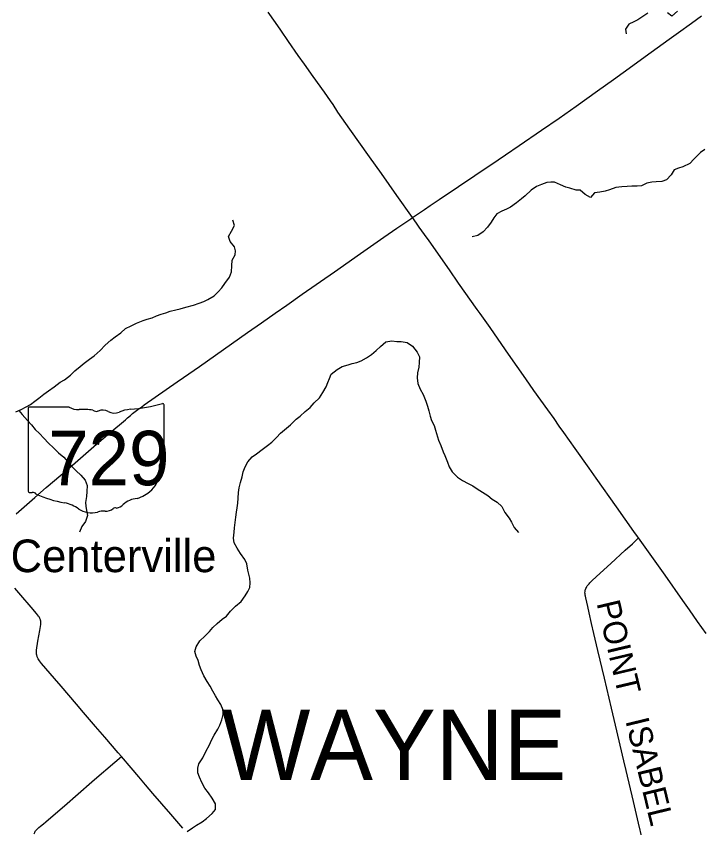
# Model space of a CAD drawing. Extents: x 0 to 34, y 0 to 22.
# Drawn here: x 3.432 to 5.101, y 18.098 to 20.064 of the extents above; entities that cross this region are included whole.
import ezdxf

# ---------------------------------------------------------------- set-up
doc = ezdxf.new("R2010")
doc.units = 0
for name, color, linetype in [('GM_X_County_Road', 7, 'Continuous'), ('GM_X_Minor_River', 7, 'Continuous'), ('GM_X_State_Location', 7, 'Continuous'), ('GM_X_State_Route', 7, 'Continuous'), ('GM_X_State_Shield', 7, 'Continuous'), ('GM_X_Township_Road', 7, 'Continuous'), ('GM_X_Township_Road_Text', 7, 'Continuous'), ('GM_X_Township_Text', 7, 'Continuous'), ('GM_X_Unincorporated_Text', 7, 'Continuous')]:
    doc.layers.add(name, color=color, linetype=linetype)

msp = doc.modelspace()

# ---------------------------------------------------------------- linework, layer by layer
at = {"layer": 'GM_X_County_Road'}
for points in [[(3.6866, 18.27), (3.6787, 18.2792), (3.6462, 18.3169), (3.6242, 18.3429), (3.595, 18.3769), (3.5777, 18.3972), (3.5405, 18.4406), (3.5248, 18.4591), (3.4932, 18.4958), (3.4883, 18.5021), (3.4852, 18.5067), (3.4843, 18.5083), (3.4835, 18.5099), (3.4826, 18.5117), (3.4821, 18.5132), (3.4817, 18.5146), (3.4813, 18.5161), (3.4811, 18.5179), (3.4808, 18.5197), (3.4808, 18.5217), (3.4807, 18.5239), (3.481, 18.5282), (3.4843, 18.5496), (3.4892, 18.5759), (3.4915, 18.59), (3.4916, 18.5918), (3.4917, 18.5938), (3.4917, 18.5952), (3.4915, 18.5971), (3.4912, 18.5985), (3.4908, 18.6002), (3.4903, 18.6017), (3.4898, 18.6033), (3.4889, 18.605), (3.4881, 18.6067), (3.4869, 18.6085), (3.4856, 18.6104), (3.4806, 18.6168), (3.4678, 18.6321), (3.4432, 18.6609), (3.4283, 18.6784)], [(3.4749, 18.0827), (3.4756, 18.0847), (3.4764, 18.0862), (3.4771, 18.0877), (3.4779, 18.0888), (3.4786, 18.0899), (3.4795, 18.091), (3.4808, 18.0924), (3.4827, 18.0944), (3.4864, 18.0979), (3.4902, 18.1011), (3.4974, 18.1071), (3.5031, 18.1119), (3.5555, 18.1568), (3.5751, 18.174), (3.6216, 18.2143), (3.6711, 18.2567), (3.6866, 18.27)], [(3.8358, 18.0965), (3.8061, 18.1308), (3.7632, 18.1807), (3.7454, 18.2014), (3.7288, 18.2207), (3.7103, 18.2425), (3.6866, 18.27)]]:
    msp.add_lwpolyline(points, dxfattribs=at)
at = {"layer": 'GM_X_Minor_River'}
for points in [[(5.0344, 20.0759), (5.021, 20.0635), (5.0105, 20.0723)], [(4.963, 20.0715), (4.9508, 20.0633), (4.9386, 20.0554), (4.929, 20.0505), (4.9165, 20.0445), (4.9088, 20.0324), (4.9102, 20.021)], [(5.1009, 19.7409), (5.0902, 19.7334), (5.0741, 19.7172), (5.0642, 19.707), (5.0474, 19.6992), (5.0375, 19.6958), (5.0269, 19.6913), (5.0195, 19.6792), (5.0084, 19.6676), (4.997, 19.6631), (4.9833, 19.6624), (4.9727, 19.6621), (4.9605, 19.6592), (4.9472, 19.6532), (4.9369, 19.6521), (4.9236, 19.6519), (4.9126, 19.6512), (4.8997, 19.6505), (4.8856, 19.6487), (4.8696, 19.6428), (4.8594, 19.6398), (4.8468, 19.6372), (4.8335, 19.6362), (4.8239, 19.6245), (4.8107, 19.6322), (4.7986, 19.6422), (4.7891, 19.6426), (4.774, 19.6469), (4.7641, 19.65), (4.7513, 19.655), (4.7369, 19.6616), (4.7274, 19.6621), (4.7179, 19.6606), (4.7053, 19.6561), (4.6927, 19.6513), (4.6801, 19.6423), (4.6653, 19.6289)], [(4.6653, 19.6289), (4.6567, 19.6214), (4.6444, 19.612), (4.6298, 19.6008), (4.6203, 19.5963), (4.6092, 19.5915), (4.5969, 19.5852), (4.5896, 19.5754), (4.5826, 19.5648), (4.5741, 19.5524), (4.5637, 19.5411), (4.5506, 19.5329), (4.5373, 19.5289)], [(3.4311, 19.1055), (3.4434, 19.1111), (3.4556, 19.1178), (3.466, 19.1234), (3.4767, 19.1308), (3.4863, 19.1383), (3.499, 19.1481), (3.5097, 19.1559), (3.5236, 19.1657), (3.5382, 19.1769), (3.5489, 19.1825), (3.5635, 19.1941), (3.5735, 19.2046), (3.5866, 19.2155), (3.5962, 19.223), (3.6096, 19.2327), (3.6207, 19.2413), (3.635, 19.2541), (3.6469, 19.2665), (3.6607, 19.2789), (3.6719, 19.2871), (3.6849, 19.2964), (3.6968, 19.3073), (3.7102, 19.314), (3.7233, 19.3199), (3.7397, 19.3266), (3.7492, 19.3295), (3.7611, 19.3332), (3.7714, 19.3376), (3.7833, 19.3421), (3.7943, 19.3454), (3.805, 19.349), (3.8184, 19.3527), (3.8294, 19.3548), (3.8428, 19.3585), (3.8611, 19.3636), (3.8753, 19.3684), (3.8863, 19.3724), (3.8959, 19.3776), (3.9116, 19.3866), (3.9216, 19.396), (3.9301, 19.4058), (3.9375, 19.4163), (3.9487, 19.4318), (3.9534, 19.4446), (3.954, 19.4594), (3.9553, 19.4724), (3.9623, 19.4856), (3.9631, 19.4951), (3.9606, 19.505), (3.9501, 19.518), (3.9464, 19.5302), (3.9534, 19.543), (3.9608, 19.5566), (3.9568, 19.57)], [(4.0039, 18.9961), (4.0139, 19.0032), (4.0278, 19.0144), (4.0404, 19.0234), (4.0516, 19.032), (4.0623, 19.0429), (4.0724, 19.0535), (4.0866, 19.0655), (4.0962, 19.0741), (4.11, 19.0872), (4.1197, 19.0951), (4.132, 19.1064), (4.1443, 19.1161), (4.1543, 19.127), (4.167, 19.139), (4.1747, 19.1522), (4.1829, 19.1662), (4.1872, 19.1764), (4.1908, 19.1862), (4.1954, 19.1965), (4.2093, 19.2081), (4.2219, 19.2148), (4.236, 19.2192), (4.246, 19.2225), (4.2574, 19.225), (4.2677, 19.2291), (4.2804, 19.2365), (4.2926, 19.244), (4.3046, 19.2537), (4.315, 19.2639), (4.3276, 19.2748), (4.3418, 19.2776), (4.3543, 19.2756), (4.3649, 19.2755), (4.379, 19.273), (4.3922, 19.2645), (4.4034, 19.2496), (4.4094, 19.2389), (4.4088, 19.2252), (4.4076, 19.2138), (4.4047, 19.2002), (4.4035, 19.188), (4.4056, 19.1736), (4.4107, 19.1606), (4.4178, 19.1472), (4.4248, 19.1312), (4.4285, 19.1194), (4.4318, 19.1075), (4.4354, 19.095), (4.4387, 19.0847), (4.4447, 19.0724), (4.448, 19.061), (4.4557, 19.037), (4.4612, 19.024), (4.4667, 19.0087), (4.4704, 18.9992), (4.4771, 18.9832), (4.4808, 18.9721), (4.4882, 18.9599), (4.5014, 18.9468), (4.5134, 18.9387), (4.5274, 18.9313), (4.5384, 18.9262), (4.5494, 18.9189), (4.5622, 18.9108), (4.575, 18.903), (4.5852, 18.8938), (4.5973, 18.8864), (4.6089, 18.8757), (4.6164, 18.8612), (4.6269, 18.8477), (4.6325, 18.8378), (4.6388, 18.8248), (4.6489, 18.8129)], [(3.4383, 19.1088), (3.4459, 19.0985), (3.4587, 19.0847), (3.4684, 19.0736), (3.4774, 19.0624), (3.488, 19.0525), (3.4985, 19.0417), (3.5101, 19.0294), (3.5218, 19.0183), (3.5342, 19.0063), (3.5474, 18.9952), (3.5575, 18.9833), (3.5654, 18.9733), (3.5767, 18.9622), (3.5883, 18.9522), (3.5992, 18.9399), (3.6036, 18.9269), (3.6031, 18.9125), (3.6018, 18.9003), (3.5997, 18.8859), (3.6007, 18.8764), (3.6021, 18.8665), (3.6043, 18.854), (3.5999, 18.8399), (3.591, 18.8275), (3.5851, 18.8135)], [(3.8461, 18.0884), (3.8588, 18.0977), (3.8688, 18.1037), (3.8822, 18.1119), (3.8933, 18.1197), (3.9068, 18.1321), (3.9149, 18.1419), (3.9147, 18.1556), (3.9065, 18.169), (3.8975, 18.182), (3.8889, 18.1935), (3.8814, 18.2073), (3.8763, 18.2206), (3.8718, 18.2305), (3.8716, 18.2423), (3.8744, 18.2525), (3.8841, 18.2672), (3.8915, 18.2827), (3.9, 18.2982), (3.9047, 18.3096), (3.9113, 18.322), (3.9203, 18.3364), (3.925, 18.3462), (3.9304, 18.3594), (3.9333, 18.3719), (3.9334, 18.3829), (3.9275, 18.3963), (3.9204, 18.4074), (3.9144, 18.417), (3.9085, 18.4288), (3.9017, 18.4407), (3.8943, 18.4521), (3.8868, 18.4655), (3.8798, 18.48), (3.8761, 18.4907), (3.8728, 18.5029), (3.868, 18.5132), (3.8647, 18.5247), (3.8679, 18.536), (3.8764, 18.5504), (3.8891, 18.562), (3.9003, 18.5733), (3.908, 18.5831), (3.9184, 18.5921), (3.9311, 18.6026), (3.9418, 18.61), (3.9515, 18.6221), (3.9631, 18.6349), (3.9773, 18.6457), (3.9866, 18.6597), (3.9932, 18.6699), (3.9979, 18.6801), (3.9991, 18.6907), (3.9977, 18.7021), (3.9952, 18.712), (3.993, 18.7219), (3.9909, 18.7368), (3.9861, 18.7474), (3.9753, 18.762), (3.967, 18.7754), (3.9603, 18.7876), (3.9582, 18.7994), (3.9599, 18.8138), (3.9612, 18.8245), (3.9625, 18.8374), (3.9641, 18.8503), (3.9654, 18.8624), (3.9671, 18.8727), (3.9691, 18.8844), (3.97, 18.8958), (3.9706, 18.9099), (3.9718, 18.9209), (3.975, 18.9341), (3.979, 18.9477), (3.9822, 18.9599), (3.9869, 18.9724), (3.9931, 18.9841), (4.0039, 18.9961)]]:
    msp.add_lwpolyline(points, dxfattribs=at)
at = {"layer": 'GM_X_State_Route'}
for points in [[(4.4087, 19.5527), (4.4016, 19.5626), (4.3921, 19.5761), (4.3545, 19.6298), (4.3169, 19.6831), (4.288, 19.7235), (4.2406, 19.7905), (4.2117, 19.8317), (4.1996, 19.8497), (4.1935, 19.8584), (4.1786, 19.8798), (4.1517, 19.9178), (4.1304, 19.9476), (4.1154, 19.969), (4.0919, 20.0026), (4.0731, 20.0296), (4.0598, 20.0484), (4.0425, 20.0734)], [(4.3921, 19.5761), (4.4211, 19.5954), (4.4355, 19.6051), (4.4572, 19.6196), (4.5035, 19.6509), (4.5437, 19.678), (4.5711, 19.6963), (4.5824, 19.704), (4.6174, 19.7277), (4.6509, 19.7502), (4.7052, 19.7875), (4.7475, 19.8169), (4.7889, 19.8456), (4.8409, 19.8829), (4.8792, 19.9105), (4.9265, 19.9447), (4.9563, 19.9661), (5.0147, 20.0083), (5.037, 20.0242), (5.0687, 20.0471), (5.0929, 20.0646)], [(3.4315, 18.8585), (3.4767, 18.8975), (3.5044, 18.9216), (3.5548, 18.9649), (3.6261, 19.0267), (3.6582, 19.0543), (3.6962, 19.0863), (3.7014, 19.0906), (3.709, 19.0968), (3.7139, 19.1009), (3.7204, 19.1059), (3.7266, 19.1108), (3.7313, 19.1142), (3.7361, 19.1178), (3.742, 19.1219), (3.8217, 19.1776), (3.837, 19.1882), (3.8756, 19.2154), (3.9342, 19.2563), (3.992, 19.2972), (4.0263, 19.3209), (4.0593, 19.3442), (4.0873, 19.3636), (4.125, 19.39), (4.2035, 19.4448), (4.2661, 19.4886), (4.3067, 19.5172), (4.3225, 19.5281), (4.3547, 19.5504), (4.3881, 19.5733), (4.3921, 19.5761)], [(4.5562, 19.3438), (4.5492, 19.3536), (4.504, 19.4174), (4.482, 19.4491), (4.4328, 19.5192), (4.4211, 19.5353), (4.4087, 19.5527)], [(5.1045, 18.5683), (5.0834, 18.5976), (5.0634, 18.626), (5.0479, 18.6485), (5.0044, 18.7099), (4.9403, 18.7998), (4.938, 18.8029), (4.929, 18.8156), (4.8868, 18.8748), (4.8373, 18.9448), (4.8202, 18.9692), (4.7867, 19.0163), (4.759, 19.0553), (4.7482, 19.0705), (4.7354, 19.0888), (4.7202, 19.1101), (4.6868, 19.1572), (4.667, 19.1851), (4.625, 19.2452), (4.6087, 19.2686), (4.5804, 19.3094), (4.5562, 19.3438)]]:
    msp.add_lwpolyline(points, dxfattribs=at)
at = {"layer": 'GM_X_State_Shield'}
for p, q in [((3.4605, 19.1135), (3.4605, 18.9134)), ((3.5603, 19.117), (3.4638, 19.117)), ((3.7901, 19.0172), (3.7901, 19.1219)), ((3.7901, 19.0173), (3.7901, 19.0172))]:
    msp.add_line(p, q, dxfattribs=at)
for centre, major_axis, start_param, end_param in [((3.4643, 19.1139), (0.00382, 0), 1.712693, 3.28349), ((3.5833, 19.1402), (0.037, 0), 4.042523, 4.731795), ((3.5955, 19.0046), (0.133, 0), 1.404758, 1.657858), ((3.7173, 19.0558), (0.0703, 0), 1.699011, 2.107814), ((3.6727, 19.3898), (0.3495, 0), 4.814394, 5.042369), ((3.7864, 19.1223), (0.00367, 0), 6.141152, 7.989035), ((3.6257, 19.115), (0.0107, 0), 3.836095, 5.185415), ((3.6414, 19.0918), (0.0222, 0), 0.950623, 2.079405), ((3.6701, 19.1236), (0.0267, 0), 4.081561, 5.145723), ((3.7892, 19.0095), (0.00568, 0), 1.883978, 3.671073), ((3.7862, 19.0168), (0.00393, 0), 5.05454, 6.418171), ((3.7531, 18.9963), (0.0341, 0), 5.934695, 6.695948), ((3.8032, 18.9734), (0.0248, 0), 2.387724, 3.262537), ((3.6923, 18.9601), (0.0874, 0), 5.101752, 6.440018), ((3.4643, 18.913), (0.00385, 0), 3.00124, 4.508301), ((3.4649, 18.9334), (0.0294, 0), 4.665946, 4.897461), ((3.4709, 18.9018), (0.0106, 0), 0.519207, 1.627899), ((3.6047, 19.0816), (0.2524, 0), 4.195997, 4.488961), ((3.7291, 18.8572), (0.0479, 0), 1.647645, 2.488434), ((3.5295, 18.8235), (0.079, 0), 0.823519, 1.323587), ((3.6685, 18.894), (0.0282, 0), 4.937069, 5.64225), ((3.6149, 18.9009), (0.0501, 0), 4.026481, 4.996735), ((3.6439, 18.8317), (0.0412, 0), 1.495662, 1.94098), ((3.6475, 18.8859), (0.0267, 0), 4.691044, 5.507374), ((3.6717, 18.8665), (0.00752, 0), 1.147584, 2.315152)]:
    msp.add_ellipse(centre, major_axis=major_axis, ratio=0.8, start_param=start_param, end_param=end_param, dxfattribs=at)
at = {"layer": 'GM_X_Township_Road'}
msp.add_lwpolyline([(4.9493, 18.0715), (4.9405, 18.1084), (4.9281, 18.161), (4.9099, 18.2364), (4.9046, 18.2601), (4.8843, 18.3459), (4.875, 18.3872), (4.8577, 18.4603), (4.8419, 18.5268), (4.8322, 18.5686), (4.8266, 18.5922), (4.8206, 18.6182), (4.817, 18.634), (4.8121, 18.6545), (4.8113, 18.6586), (4.8108, 18.6612), (4.8106, 18.6642), (4.8104, 18.6668), (4.8107, 18.6699), (4.8112, 18.6729), (4.8118, 18.6752), (4.8126, 18.6775), (4.8138, 18.6801), (4.8149, 18.6821), (4.816, 18.6836), (4.8174, 18.6855), (4.8186, 18.6871), (4.8203, 18.6889), (4.8224, 18.6913), (4.8273, 18.696), (4.8383, 18.7061), (4.8728, 18.7375), (4.9078, 18.77), (4.9254, 18.7858), (4.9349, 18.7948), (4.9403, 18.7998)], dxfattribs=at)

# ---------------------------------------------------------------- texts
at = {"layer": 'GM_X_State_Location'}
for s in ['s', 'r']:
    msp.add_text(s, height=0.000189, dxfattribs=at).set_placement((3.6216, 19.0001))
msp.add_text('729', height=0.000189, rotation=0, dxfattribs=at).set_placement((3.5547, 18.9864))
at = {"layer": 'GM_X_State_Shield'}
msp.add_text('729', height=0.13184, dxfattribs=at).set_placement((3.509, 18.9275))
at = {"layer": 'GM_X_Township_Road_Text'}
for s, rotation, p in [('POINT', 283.2535, (4.8382, 18.642)), ('ISABEL', 283.6265, (4.908, 18.3573))]:
    msp.add_text(s, height=0.05682, rotation=rotation, dxfattribs=at).set_placement(p)
at = {"layer": 'GM_X_Township_Text'}
msp.add_text('WAYNE', height=0.17045, rotation=0, dxfattribs=at).set_placement((3.9294, 18.2131))
at = {"layer": 'GM_X_Unincorporated_Text'}
msp.add_text('Centerville', height=0.078977, rotation=0, dxfattribs=at).set_placement((3.4181, 18.7169))

doc.saveas('drawing.dxf')
